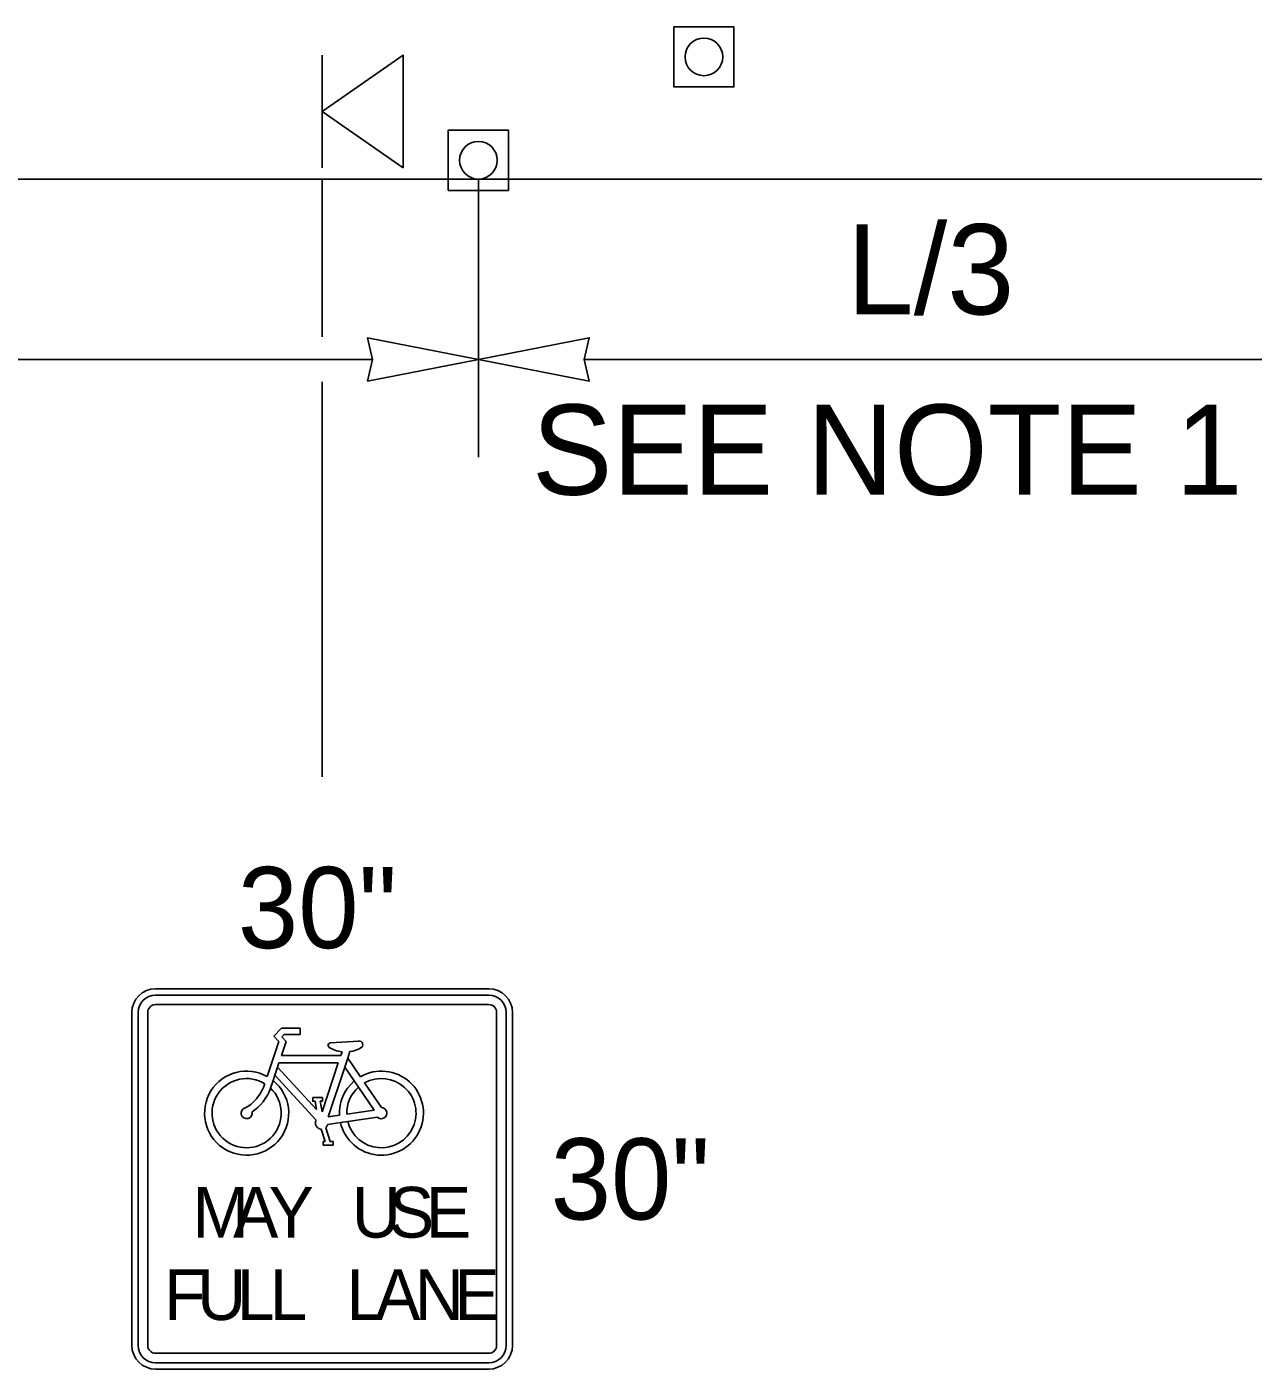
# Model space of a CAD drawing. Extents: x 99999.1 to 100055.7, y 99995 to 100013.2.
# Drawn here: x 100006.375 to 100007.462, y 100004.18 to 100005.371 of the extents above; entities that cross this region are included whole.
import ezdxf

# ---------------------------------------------------------------- set-up
doc = ezdxf.new("R2010")
doc.units = 0
for name, color, linetype in [('RD_ED_ShoulderPavedEdge', 7, 'Continuous'), ('TR_SN_ConstructionSigns', 7, 'Continuous'), ('TR_WZ_PortableSignMountBlk-Wht', 7, 'Continuous'), ('TR_WZ_TrafficCone', 7, 'Continuous'), ('TR_WZ_WorkZoneDetails', 7, 'Continuous'), ('TR_WZ_WorkZoneTextCurrent', 7, 'Continuous')]:
    doc.layers.add(name, color=color, linetype=linetype)

msp = doc.modelspace()

# ---------------------------------------------------------------- linework, layer by layer
at = {"layer": 'RD_ED_ShoulderPavedEdge'}
msp.add_line((100000.8283, 100005.2357), (100015.62, 100005.2357), dxfattribs=at)
at = {"layer": 'TR_SN_ConstructionSigns'}
for p, q in [((100006.4891, 100004.5175), (100006.7845, 100004.5175)), ((100006.7845, 100004.5175), (100006.4891, 100004.5175)), ((100006.7845, 100004.5175), (100006.4891, 100004.5175)), ((100006.7845, 100004.5119), (100006.4891, 100004.5119)), ((100006.468, 100004.2011), (100006.468, 100004.4964)), ((100006.468, 100004.4964), (100006.468, 100004.2011)), ((100006.468, 100004.4964), (100006.468, 100004.2011)), ((100006.4737, 100004.4964), (100006.4737, 100004.2011)), ((100006.4821, 100004.2011), (100006.4821, 100004.4964)), ((100006.4891, 100004.5035), (100006.7845, 100004.5035)), ((100006.7915, 100004.4964), (100006.7915, 100004.2011)), ((100006.7999, 100004.2011), (100006.7999, 100004.4964)), ((100006.8055, 100004.4964), (100006.8055, 100004.2011)), ((100006.8055, 100004.2011), (100006.8055, 100004.4964)), ((100006.8055, 100004.2011), (100006.8055, 100004.4964)), ((100006.6008, 100004.4824), (100006.5938, 100004.4754)), ((100006.6173, 100004.4824), (100006.6008, 100004.4824)), ((100006.6173, 100004.4769), (100006.6173, 100004.4824)), ((100006.5985, 100004.4707), (100006.5881, 100004.4396)), ((100006.5938, 100004.4754), (100006.5985, 100004.4707)), ((100006.6007, 100004.4582), (100006.6049, 100004.4707)), ((100006.6009, 100004.4747), (100006.6031, 100004.4769)), ((100006.6049, 100004.4707), (100006.6009, 100004.4747)), ((100006.6031, 100004.4769), (100006.6173, 100004.4769)), ((100006.6692, 100004.4711), (100006.6443, 100004.4695)), ((100006.6533, 100004.4582), (100006.6007, 100004.4582)), ((100006.6545, 100004.4616), (100006.6533, 100004.4582)), ((100006.6595, 100004.4559), (100006.6614, 100004.4617)), ((100006.5949, 100004.4407), (100006.5972, 100004.4478)), ((100006.5972, 100004.4478), (100006.5985, 100004.4517)), ((100006.6319, 100004.4102), (100006.5972, 100004.4478)), ((100006.5985, 100004.4517), (100006.6511, 100004.4517)), ((100006.6511, 100004.4517), (100006.6367, 100004.4083)), ((100006.6421, 100004.4038), (100006.6569, 100004.448)), ((100006.6595, 100004.4559), (100006.6569, 100004.448)), ((100006.6569, 100004.448), (100006.6653, 100004.4357)), ((100006.6707, 100004.4394), (100006.6595, 100004.4559)), ((100006.5933, 100004.4361), (100006.591, 100004.4293)), ((100006.5933, 100004.4361), (100006.5949, 100004.4407)), ((100006.5949, 100004.4407), (100006.6315, 100004.4009)), ((100006.6653, 100004.4357), (100006.669, 100004.4302)), ((100006.6893, 100004.4121), (100006.6744, 100004.434)), ((100006.669, 100004.4302), (100006.6828, 100004.4098)), ((100006.6372, 100004.4209), (100006.6284, 100004.4209)), ((100006.6306, 100004.4176), (100006.6319, 100004.4102)), ((100006.6367, 100004.4083), (100006.635, 100004.4176)), ((100006.635, 100004.4176), (100006.6372, 100004.4176)), ((100006.6372, 100004.4176), (100006.6372, 100004.4209)), ((100006.6416, 100004.3971), (100006.653, 100004.3988)), ((100006.6521, 100004.4053), (100006.6421, 100004.4038)), ((100006.653, 100004.3988), (100006.6595, 100004.3997)), ((100006.6828, 100004.4098), (100006.6586, 100004.4063)), ((100006.6595, 100004.3997), (100006.6858, 100004.4036)), ((100006.6358, 100004.3928), (100006.6394, 100004.382)), ((100006.644, 100004.382), (100006.64, 100004.3942)), ((100006.6394, 100004.382), (100006.6376, 100004.382)), ((100006.6376, 100004.382), (100006.6376, 100004.3788)), ((100006.6376, 100004.3788), (100006.6464, 100004.3788)), ((100006.6464, 100004.382), (100006.644, 100004.382)), ((100006.6464, 100004.3788), (100006.6464, 100004.382)), ((100006.7845, 100004.1941), (100006.4891, 100004.1941)), ((100006.4891, 100004.1856), (100006.7845, 100004.1856)), ((100006.7845, 100004.18), (100006.4891, 100004.18)), ((100006.4891, 100004.18), (100006.7845, 100004.18)), ((100006.4891, 100004.18), (100006.7845, 100004.18))]:
    msp.add_line(p, q, dxfattribs=at)
msp.add_lwpolyline([(100006.6284, 100004.4209), (100006.6284, 100004.4176), (100006.6306, 100004.4176)], dxfattribs=at)
for centre, radius, start, end in [((100006.4891, 100004.4964), 0.0211, 90, 180), ((100006.4891, 100004.4964), 0.0211, 90, 180), ((100006.4891, 100004.4964), 0.0211, 90, 180), ((100006.7845, 100004.4964), 0.0211, 0, 90), ((100006.7845, 100004.4964), 0.0211, 0, 90), ((100006.7845, 100004.4964), 0.0211, 0, 90), ((100006.4891, 100004.4964), 0.0155, 90, 180), ((100006.7845, 100004.4964), 0.0155, 0, 90), ((100006.4891, 100004.4964), 0.00703, 90, 180), ((100006.7845, 100004.4964), 0.00703, 0, 90), ((100006.6695, 100004.4679), 0.00329, 294.5519, 96.4128), ((100006.6443, 100004.4673), 0.00219, 89.3854, 243.6828), ((100006.5698, 100004.4071), 0.0373, 60.5529, 50.868), ((100006.5698, 100004.4071), 0.0307, 58.1532, 46.1649), ((100006.6893, 100004.4071), 0.0373, 130.0889, 182.8379), ((100006.6893, 100004.4071), 0.0373, 192.9622, 119.9648), ((100006.6893, 100004.4071), 0.0307, 193.937, 119.0598), ((100006.6893, 100004.4071), 0.0307, 131.3616, 181.6359), ((100006.5698, 100004.4071), 0.00493, 105.257, 14.3233), ((100006.6893, 100004.4071), 0.00493, 225.1095, 90.4672), ((100006.6363, 100004.3983), 0.00548, 151.1744, 264.8566), ((100006.6363, 100004.3983), 0.00548, 312.0053, 347.2932), ((100006.4891, 100004.2011), 0.0211, 180, 270), ((100006.4891, 100004.2011), 0.0211, 180, 270), ((100006.4891, 100004.2011), 0.0211, 180, 270), ((100006.4891, 100004.2011), 0.0155, 180, 270), ((100006.4891, 100004.2011), 0.00703, 180, 270), ((100006.7845, 100004.2011), 0.0211, 270, 0), ((100006.7845, 100004.2011), 0.0211, 270, 0), ((100006.7845, 100004.2011), 0.0155, 270, 0), ((100006.7845, 100004.2011), 0.00703, 270, 0), ((100006.7845, 100004.2011), 0.0211, 270, 0)]:
    msp.add_arc(centre, radius, start, end, dxfattribs=at)
for centre, major_axis, ratio, start_param, end_param in [((100006.6574, 100004.4724), (-0.0186, 0), 0.588235, 0.686048, 1.410588), ((100006.6574, 100004.4724), (-0.0186, 0), 0.588235, 1.786993, 2.401245), ((100006.5747, 100004.4279), (-0.0105, -0.0158), 0.413554, 0.494612, 2.170849), ((100006.5747, 100004.4279), (-0.014, -0.021), 0.55814, 0.868091, 1.989998)]:
    msp.add_ellipse(centre, major_axis=major_axis, ratio=ratio, start_param=start_param, end_param=end_param, dxfattribs=at)
at = {"layer": 'TR_WZ_PortableSignMountBlk-Wht'}
msp.add_line((100006.6368, 100005.2457), (100006.6368, 100005.3457), dxfattribs=at)
msp.add_lwpolyline([(100006.6368, 100005.2956), (100006.7086, 100005.3457), (100006.7086, 100005.2457)], close=True, dxfattribs=at)
at = {"layer": 'TR_WZ_TrafficCone'}
for points in [[(100006.9487, 100005.3707), (100007.002, 100005.3707), (100007.002, 100005.3174), (100006.9487, 100005.3174), (100006.9487, 100005.3707)], [(100006.9487, 100005.3174), (100007.002, 100005.3174), (100007.002, 100005.3707), (100006.9487, 100005.3707), (100006.9487, 100005.3174)], [(100006.7486, 100005.2791), (100006.8019, 100005.2791), (100006.8019, 100005.2257), (100006.7486, 100005.2257), (100006.7486, 100005.2791)], [(100006.7486, 100005.2257), (100006.8019, 100005.2257), (100006.8019, 100005.2791), (100006.7486, 100005.2791), (100006.7486, 100005.2257)]]:
    msp.add_lwpolyline(points, dxfattribs=at)
for centre in [(100006.9753, 100005.3441), (100006.7753, 100005.2524)]:
    msp.add_circle(centre, 0.0167, dxfattribs=at)
at = {"layer": 'TR_WZ_WorkZoneDetails'}
for p, q in [((100006.6368, 100005.2357), (100006.6368, 100005.0957)), ((100006.7753, 100005.2357), (100006.7753, 100004.9891)), ((100006.6815, 100005.0757), (100005.869, 100005.0757)), ((100007.4815, 100005.0757), (100006.869, 100005.0757)), ((100006.6368, 100005.0557), (100006.6368, 100004.7055))]:
    msp.add_line(p, q, dxfattribs=at)
for points in [[(100006.7753, 100005.0757), (100006.677, 100005.095), (100006.6815, 100005.0757), (100006.677, 100005.0565)], [(100006.7753, 100005.0757), (100006.8736, 100005.095), (100006.869, 100005.0757), (100006.8736, 100005.0565)]]:
    msp.add_lwpolyline(points, close=True, dxfattribs=at)

# ---------------------------------------------------------------- texts
at = {"layer": 'TR_SN_ConstructionSigns'}
for p in [(100006.562, 100004.5535), (100006.8394, 100004.3128)]:
    msp.add_text('30"', height=0.072, rotation=360, dxfattribs=at).set_placement(p)
for s, p in [('M', (100006.5218, 100004.2967)), ('A', (100006.5578, 100004.2967)), ('Y', (100006.5893, 100004.2967)), ('U', (100006.6631, 100004.2967)), ('S', (100006.696, 100004.2967)), ('E', (100006.7288, 100004.2967)), ('F', (100006.4966, 100004.2236)), ('U', (100006.5259, 100004.2236)), ('L', (100006.561, 100004.2236)), ('L', (100006.5902, 100004.2236)), ('L', (100006.6582, 100004.2236)), ('A', (100006.6838, 100004.2236)), ('N', (100006.7189, 100004.2236)), ('E', (100006.754, 100004.2236))]:
    msp.add_text(s, height=0.045, dxfattribs=at).set_placement(p)
at = {"layer": 'TR_WZ_WorkZoneTextCurrent'}
for s, p in [('L/3', (100007.1019, 100005.1157)), ('SEE NOTE 1', (100006.8228, 100004.9557))]:
    msp.add_text(s, height=0.08, rotation=360, dxfattribs=at).set_placement(p)

doc.saveas('drawing.dxf')
